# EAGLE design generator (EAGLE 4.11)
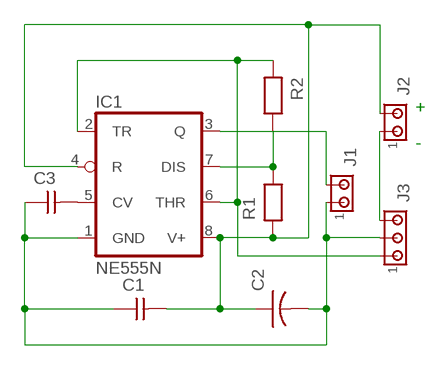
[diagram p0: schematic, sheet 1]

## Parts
C1  CAPNP-5  [C-5]
C2  CAP-5  [C-5]
C3  CAPNP-5  [C-5]
IC1  NE555N  [DIL08]
J1  MTA02-100  [10X02MTA]
J2  MTA02-100  [10X02MTA]
J3  MTA03-100  [10X03MTA]
R1  RESEU-5  [R-5]
R2  RESEU-5  [R-5]

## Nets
N$1: C1.2 C2.1 IC1.4(R) IC1.8(V+) J2.2 R1.1
N$2: IC1.7(DIS) R1.2 R2.2
N$3: IC1.2(TR) IC1.6(THR) J3.1 R2.1
N$4: C1.1 C2.2 C3.1 IC1.1(GND) J1.1 J3.2
N$5: C3.2 IC1.5(CV)
N$7: J2.1 J3.3
N$11: IC1.3(Q) J1.2

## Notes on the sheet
- +
- -

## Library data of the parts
C1 C3 = discrete:CAPNP-5
C2 = discrete:CAP-5
IC1 = linear:*555: TIMER
J1 J2 = con-amp:MTA02-100: AMP connector
J3 = con-amp:MTA03-100: AMP connector
R1 R2 = discrete:RESEU-5

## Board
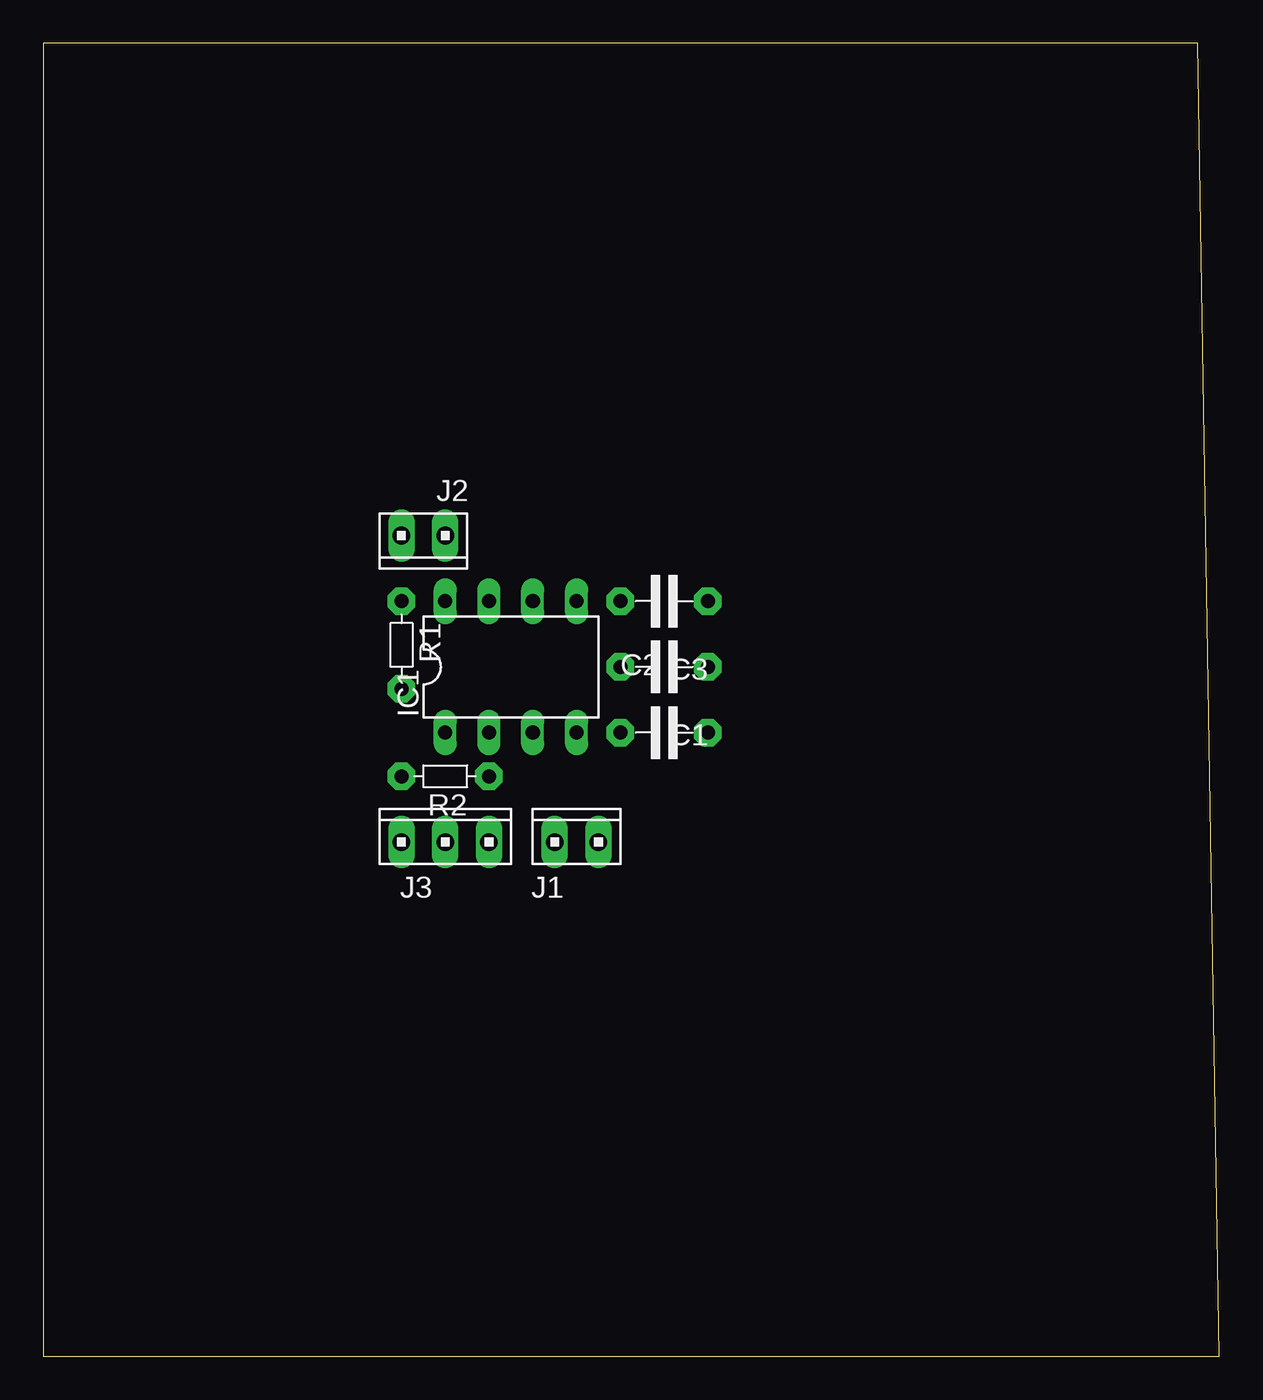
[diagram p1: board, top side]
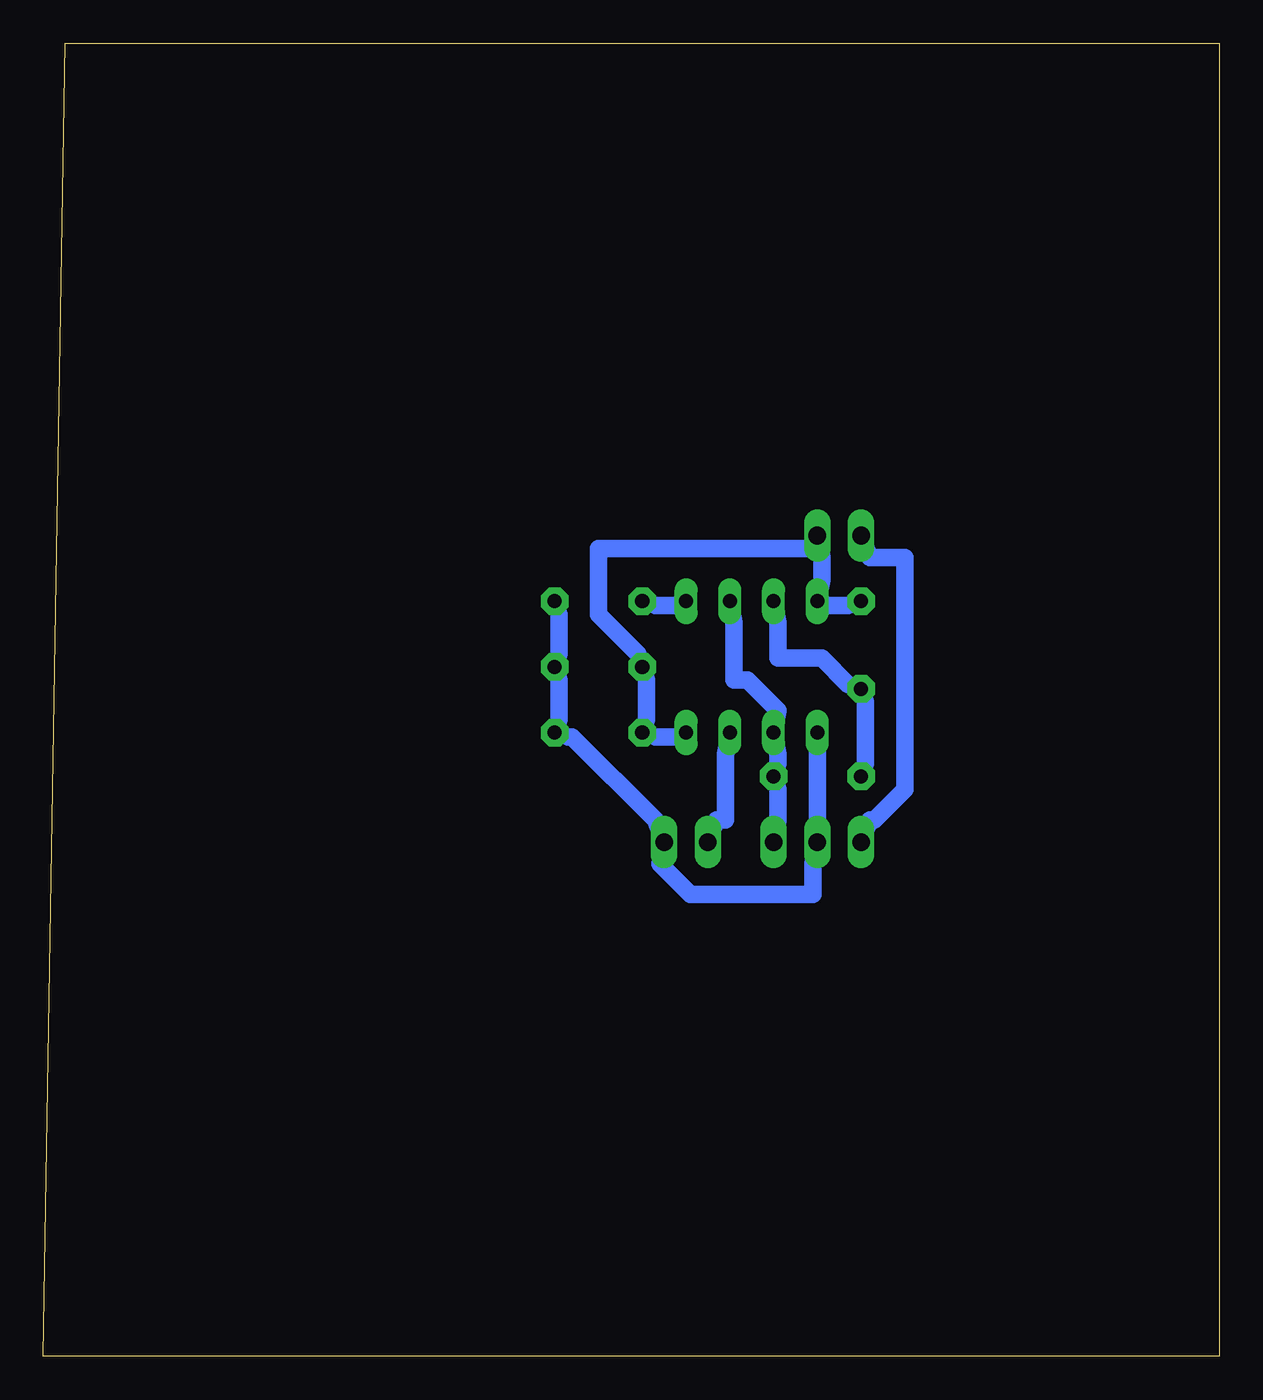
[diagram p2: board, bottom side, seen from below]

Size 68.25 x 76.19 mm. Coordinates in mm from the lower left corner, seen from the top.
Outline: 0,0 68.25,0 66.98,76.19 0,76.19 0,0
Copper layers 16: Bottom 0.035mm
Design rules "default": minimum track width 40mil, minimum drill 24mil, track to track 40mil, track to pad 40mil, pad to pad 40mil, via to via 40mil, smd to smd 8mil, copper to edge 40mil, drill to drill 8mil, minimum pad ring 10mil, minimum via ring 8mil, stop-mask expansion 4mil, vias tented up to drill 0mil, thermal gap 10mil

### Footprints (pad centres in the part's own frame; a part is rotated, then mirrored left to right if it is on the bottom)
C-5 = drill 0.813 pad 1.6 octagon: 1 -2.54,0; 2 2.54,0
DIL08 = drill 0.813 long: 1 -3.81,-3.81; 2 -1.27,-3.81; 3 1.27,-3.81; 4 3.81,-3.81; 5 3.81,3.81; 6 1.27,3.81; 7 -1.27,3.81; 8 -3.81,3.81
10X02MTA = drill 1.016 long: 1 1.27,0; 2 -1.27,0
10X03MTA = drill 1.016 long: 1 2.54,0; 2 0,0; 3 -2.54,0
R-5 = drill 0.813 pad 1.6 octagon: 1 -2.54,0; 2 2.54,0

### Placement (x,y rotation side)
C1  36.03,40 180 top
C2  36.03,36.19 0 top
C3  36.03,43.81 180 top
IC1  27.14,40 0 top
J1  30.95,29.84 0 top
J2  22.06,47.62 180 top
J3  23.33,29.84 0 top
R1  20.79,41.27 270 top
R2  23.33,33.65 180 top

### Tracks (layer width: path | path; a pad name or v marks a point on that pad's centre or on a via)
N$1
  Bottom 1.016: IC1.4 31.46,35.94 32.73,35.94 C2.1 33.24,36.95 33.24,39.24 C1.2 33.74,40.76 36.03,43.05 36.03,46.86 23.84,46.86 J2.2 23.08,46.35 23.08,45.08 IC1.8 22.82,43.56 21.55,43.56 R1.1
N$2
  Bottom 1.016: IC1.7 25.62,42.54 25.62,40.51 23.08,40.51 21.55,38.98 R1.2 20.54,37.97 20.54,34.41 R2.2
N$3
  Bottom 1.016: IC1.6 28.16,42.54 28.16,39.24 27.39,39.24 25.62,37.46 IC1.2 25.62,34.92 25.62,34.41 R2.1 25.62,32.89 25.62,31.11 J3.1
N$4
  Bottom 1.016: IC1.1 J3.2 23.58,28.57 23.58,26.79 30.7,26.79 32.47,28.57 J1.1 32.73,31.11 37.55,35.94 37.81,35.94 C2.2 38.32,36.95 38.32,39.24 C1.1 38.32,40.76 38.32,43.05 C3.1
N$5
  Bottom 1.016: IC1.5 31.46,43.56 32.73,43.56 C3.2
N$7
  Bottom 1.016: J3.3 20.28,31.11 20.03,31.11 18.25,32.89 18.25,46.35 20.28,46.35 J2.1
N$11
  Bottom 1.016: IC1.3 28.66,34.92 28.66,31.11 29.17,31.11 J1.2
